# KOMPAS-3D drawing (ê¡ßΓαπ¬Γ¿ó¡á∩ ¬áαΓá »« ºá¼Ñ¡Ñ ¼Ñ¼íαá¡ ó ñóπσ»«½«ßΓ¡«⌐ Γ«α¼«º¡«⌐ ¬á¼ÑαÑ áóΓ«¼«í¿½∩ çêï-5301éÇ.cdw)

Referenced files in C:\Вороровано\Мои документы\: Технологическая карта.cdw
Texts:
  Инструктивная карта по замене мембран в   двухполостной тормозной  камере автомобиля  ЗИЛ-5301ВА
  133 1 134 1 135 1 136 0 50 1|SPDS|133 1 134 1 135 1 136 0 50 1
  125 1 126 1 127 1 128 0 50 1|SPDS|125 1 126 1 127 1 128 0 50 1
  129 1 130 1 131 1 132 0 50 1|SPDS|129 1 130 1 131 1 132 0 50 1
  Содержание перехода
  Эскиз
  Оборудование и
  инструмент
  Номер
  перехода
  операции,
  трудоёмкость
  тормозной камеры, 4.0 чел-мин
  005       Установить автомобиль на пост ТР
  010       Включить стояночный тормоз
  015       Снять с кронштейна двухполостную
  тормозную камеру.
  020      Отсоединить двухполостную тормозную
  камеру от главного тормозного цилиндра.
  Рисунок 1 -двухполостная тормозная камера
  1-шток, 2-корпус первой камеры, 3-пружина,
  4,9-хомуты, 5,8-болт, 6-корпус второй камеры,
  005      Зажать двухполостную тормозную камеру
  в специальном приспособлении с винтом.
  010      Отвернуть болт М6 (5) хомута (4).
  015      Снять хомуты (4).
  020     Отпуская винт приспособления разделить
  корпуса (2) и (6).
  025     Вынуть шток (1), мембрану (7), пружину (3).
  030     Отвернуть болт М6 (8) хомута (9).
  035     Снять хомуты (9).
  040     Вынуть мембрану (7) и крышку (10)
  005      Установить мембрану (7) вторичной камеры
  и крышку (10).
  010     Установить хомут (9), закрепив его
  болтом М6 (8) гайкой М6 и пружинной
  шайбой.
  015     Установить камеру в приспособление с винтом
  020    Установить мембрану (7) первичной камеры,
  шток (1), пружину (3), корпус (2) и зажать их
  в приспособлении.
  025    Закрепить хомутом (4).
  030     Закрепить болтом М6 (5), гайкой М6, и
  пружинной шайбой
  005      Соединить двухполостную тормозную камеру
  с главным тормозным цилиндром.
  010      Присоединить к кронштейну на кабине.
  005 Установка двухполостной
  тормозной камеры, 8.0 чел-мин
  Рисунок 2 - Приспособление для разборки
  двухполостной тормозной камеры.
  1-Винт, 2-гайка, 3-верхняя плита,
  4-стойка, 5-подпятник, 6-нижняя плита.
  Замена мембраны в двухполостной тормозной камере
  Автомобиль ЗИЛ - 5301ВА
  Общая трудоёмкость 110 чел-мин.
  Исполнитель - слесарь по ремонту автомобилей 4-го разряда
  Приспособление для разборки двухполостной тормозной камеры мод. И 804.33.000.
  Ключ гаечный кольцевой 6, 13 мм ГОСТ 2906-80.
  Пассатижи комбинированные ГОСТ 17438-72.
  Устройство для сжатия пружины.
  Инструктивная карта
  по замене мембран в
  двухполостной тормозной
  камере автомобиля
  ЗИЛ-5301ВА
Dimensions and other numbers on the sheet: 005 Снятие двухполостной; 010 Разборка; 10чел-мин; 5; 4; 3; 2; 6; 1; 7; 8; 9; 10; 7-мембраны, 10-крышка.; 010 Сборка; 25чел-мин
